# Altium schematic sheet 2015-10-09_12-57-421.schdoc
size 628 x 193 mm; SheetNumber: 1; SheetTotal: 1
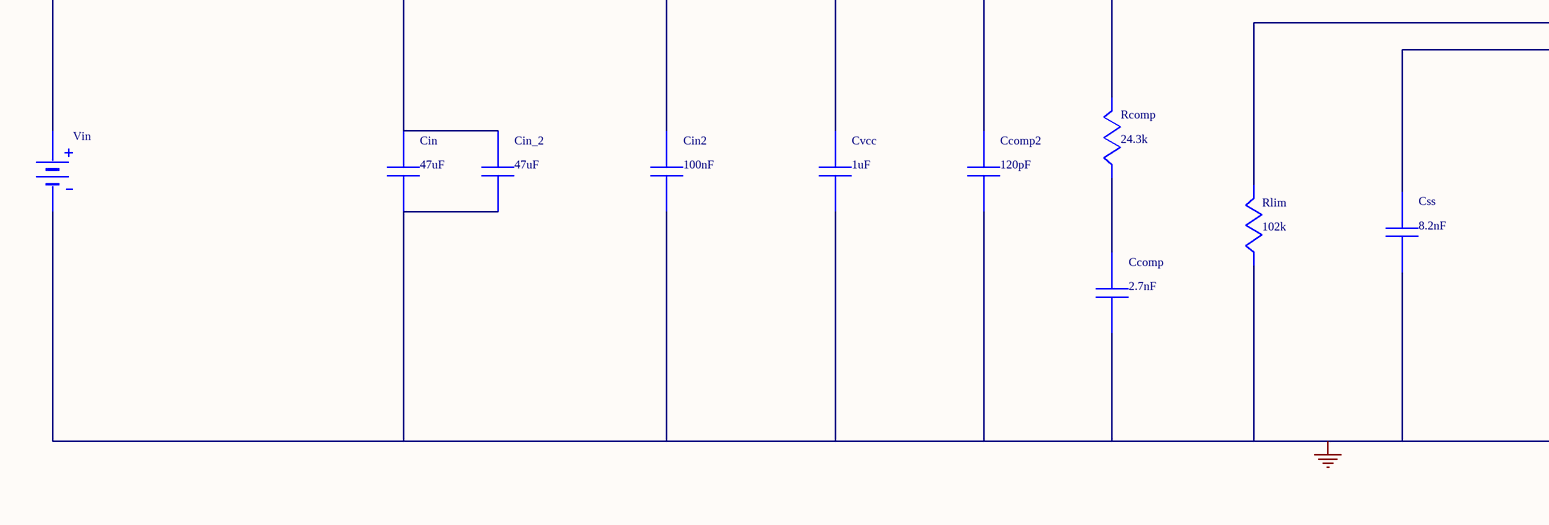
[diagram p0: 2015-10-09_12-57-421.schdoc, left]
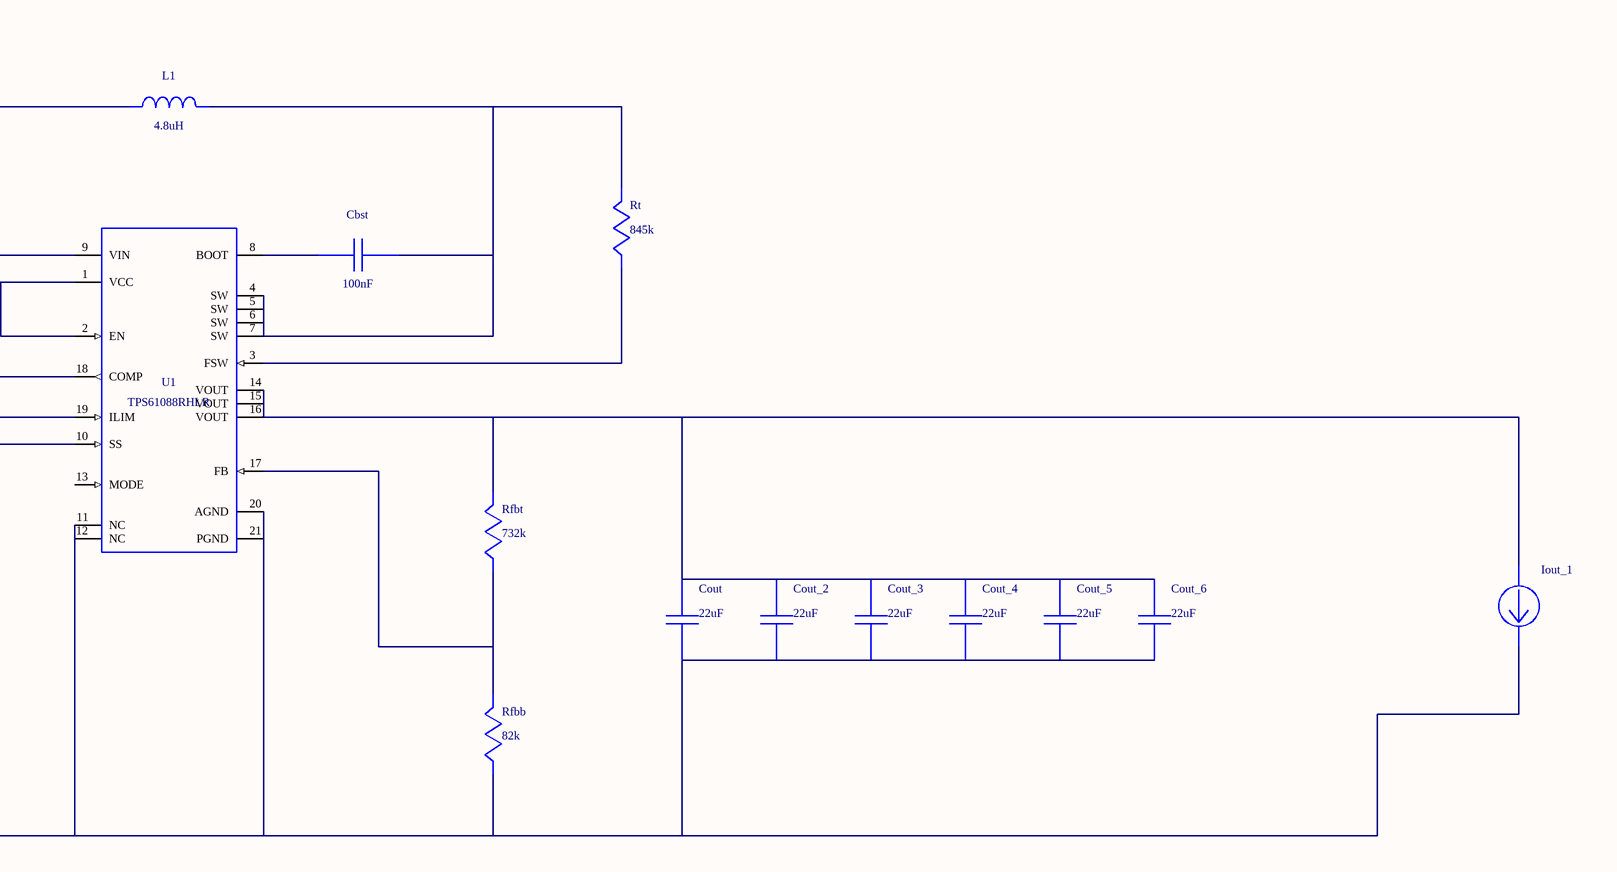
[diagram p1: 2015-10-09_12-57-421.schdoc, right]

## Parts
Cbst  value 100nF  (hidden comment: 08053C104KAT2A)
Ccomp  value 2.7nF  (hidden comment: CC0805KRX7R9BB272)
Ccomp2  value 120pF  (hidden comment: CC0805JRNPO9BN121)
Cin  value 47uF  (hidden comment: GRM32ER61C476ME15L)
Cin2  value 100nF  (hidden comment: GRM155R61C104KA88D)
Cin_2  value 47uF  (hidden comment: GRM32ER61C476ME15L)
Cout  value 22uF  (hidden comment: GRM32ER61E226KE15L)
Cout_2  value 22uF  (hidden comment: GRM32ER61E226KE15L)
Cout_3  value 22uF  (hidden comment: GRM32ER61E226KE15L)
Cout_4  value 22uF  (hidden comment: GRM32ER61E226KE15L)
Cout_5  value 22uF  (hidden comment: GRM32ER61E226KE15L)
Cout_6  value 22uF  (hidden comment: GRM32ER61E226KE15L)
Css  value 8.2nF  (hidden comment: GRM155R71C822KA01D)
Cvcc  value 1uF  (hidden comment: C1608X5R1A105K)
Iout_1  WB_CURRENT_LOAD  (value not drawn)
L1  value 4.8uH  (hidden comment: ETQPAF4R8HFA)
Rcomp  value 24.3k  (hidden comment: ERJ-6ENF2432V)
Rfbb  value 82k  (hidden comment: RC0603FR-0782KL)
Rfbt  value 732k  (hidden comment: CRCW0402732KFKED)
Rlim  value 102k  (hidden comment: ERJ-8ENF1023V)
Rt  value 845k  (hidden comment: ERJ-8ENF8453V)
U1  TPS61088RHLR
Vin  WB_BATTERY  (value not drawn)

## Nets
0: Ccomp.2 Ccomp2.2 Cin.2 Cin2.2 Cin_2.2 Cout.2 Cout_2.2 Cout_3.2 Cout_4.2 Cout_5.2 Cout_6.2 Css.2 Cvcc.2 Iout_1.2(-) Rfbb.2 Rlim.2 U1.11(NC) U1.12(NC) U1.20(AGND) U1.21(PGND) Vin.2(-)
NetCbst_1: Cbst.1 U1.8(BOOT)
NetCbst_2: Cbst.2 L1.2 Rt.1 U1.4(SW) U1.5(SW) U1.6(SW) U1.7(SW)
NetCcomp2_1: Ccomp2.1 Rcomp.1 U1.18(COMP)
NetCcomp_1: Ccomp.1 Rcomp.2
NetCin_1: Cin.1 Cin2.1 Cin_2.1 L1.1 U1.9(VIN) Vin.1(+)
NetCout_1: Cout.1 Cout_2.1 Cout_3.1 Cout_4.1 Cout_5.1 Cout_6.1 Iout_1.1(+) Rfbt.1 U1.14(VOUT) U1.15(VOUT) U1.16(VOUT)
NetCss_1: Css.1 U1.10(SS)
NetCvcc_1: Cvcc.1 U1.1(VCC) U1.2(EN)
NetRfbb_1: Rfbb.1 Rfbt.2 U1.17(FB)
NetRlim_1: Rlim.1 U1.19(ILIM)
NetRt_2: Rt.2 U1.3(FSW)

Not connected (* = marked no-connect by the designer): U1 13(MODE)

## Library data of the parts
Cbst = 08053C104KAT2A: Manufacturer Name: AVX
Ccomp = CC0805KRX7R9BB272: CC0805KRX7R9BB27; Manufacturer Name: Yageo America
Ccomp2 = CC0805JRNPO9BN121: CC0805JRNPO9BN12; Manufacturer Name: Yageo America
Cin Cin_2 = GRM32ER61C476ME15L: GRM32ER61C476ME1; Manufacturer Name: MuRata
Cin2 = GRM155R61C104KA88D: GRM155R61C104KA8; Manufacturer Name: MuRata
Cout Cout_2-Cout_6 = GRM32ER61E226KE15L: GRM32ER61E226KE1; Manufacturer Name: MuRata
Css = GRM155R71C822KA01D: GRM155R71C822KA0; Manufacturer Name: MuRata
Cvcc = C1608X5R1A105K: Manufacturer Name: TDK
Iout_1 = WB_CURRENT_LOAD: Value: UNLISTED
L1 = ETQPAF4R8HFA: Manufacturer Name: Panasonic
Rcomp = ERJ-6ENF2432V: Manufacturer Name: Panasonic
Rfbb = RC0603FR-0782KL: Manufacturer Name: Yageo America
Rfbt = CRCW0402732KFKED: Manufacturer Name: Vishay-Dale
Rlim = ERJ-8ENF1023V: Manufacturer Name: Panasonic
Rt = ERJ-8ENF8453V: Manufacturer Name: Panasonic
U1 = TPS61088RHLR: Manufacturer Name: Texas Instruments; Value: UNLISTED
Vin = WB_BATTERY: Value: UNLISTED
